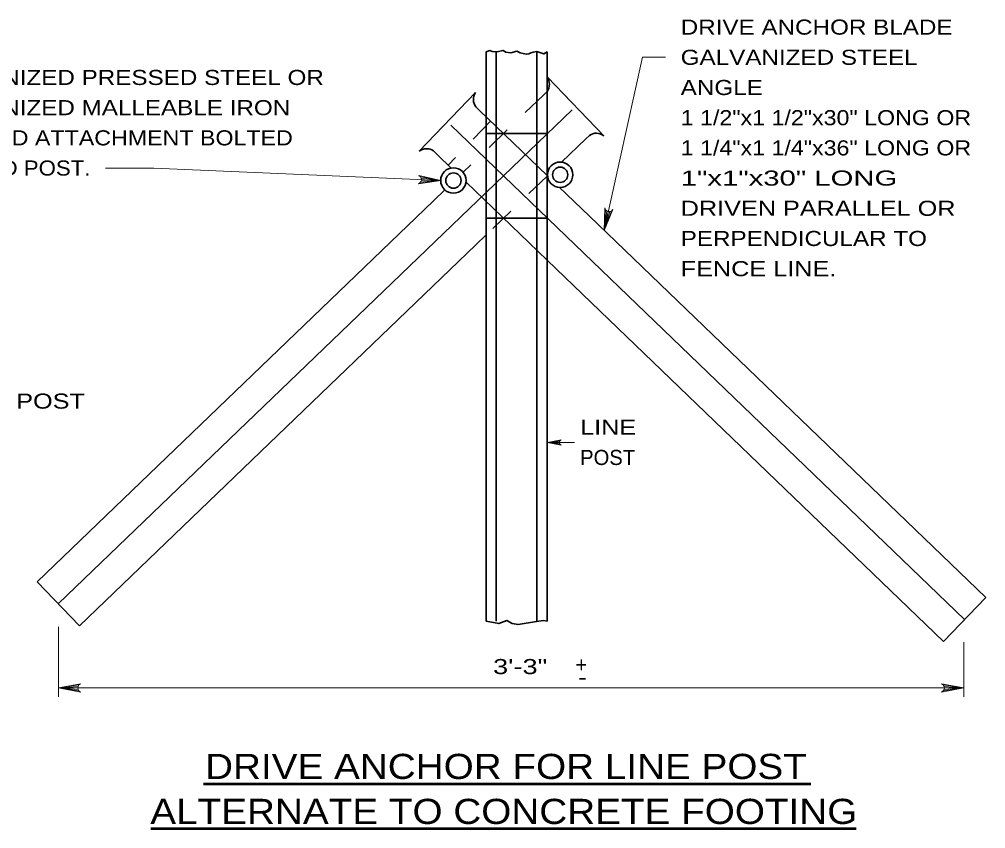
# Model space of a CAD drawing. Extents: x -29.89 to -22.78, y 99.65 to 109.34.
# Drawn here: x -26.626 to -22.784, y 106.12 to 109.336 of the extents above; entities that cross this region are included whole.
import ezdxf
from ezdxf.enums import TextEntityAlignment as Align

# ---------------------------------------------------------------- set-up
doc = ezdxf.new("R2010")
doc.units = 0
doc.header["$LTSCALE"] = 0.024
doc.linetypes.add('SHORT_DASHED', pattern=[2.7, 1.5, -1.2])
for name, color, linetype, lineweight in [('1', 7, 'Continuous', 35), ('10', 7, 'Continuous', 13), ('12', 7, 'Continuous', 53)]:
    doc.layers.add(name, color=color, linetype=linetype, lineweight=lineweight)

msp = doc.modelspace()

# ---------------------------------------------------------------- linework, layer by layer
at = {"layer": '1'}
for p, q in [((-24.7701, 106.94477), (-24.7701, 109.2074)), ((-24.72971, 106.94477), (-24.72971, 109.2074)), ((-24.56808, 106.94477), (-24.56808, 109.2074)), ((-24.52769, 106.94477), (-24.52769, 109.2074)), ((-24.52656, 109.1066), (-24.30254, 108.87362)), ((-24.81221, 109.04504), (-25.03625, 108.81206)), ((-26.47085, 107.0129), (-24.4284, 108.97679)), ((-24.79654, 108.97392), (-24.8111, 108.98792)), ((-24.52769, 108.71542), (-24.79654, 108.97392)), ((-22.86792, 106.95133), (-24.91037, 108.91523)), ((-24.7701, 108.88246), (-24.52769, 108.88246)), ((-24.7701, 106.94477), (-24.7701, 108.86681)), ((-24.72971, 106.94477), (-24.72971, 108.86681)), ((-24.56808, 106.94477), (-24.56808, 108.86681)), ((-24.52769, 106.94477), (-24.52769, 108.86681)), ((-24.46981, 108.76883), (-24.37423, 108.86073)), ((-24.37423, 108.86073), (-24.35967, 108.87473)), ((-24.96456, 108.79917), (-24.97912, 108.81317)), ((-24.90865, 108.7454), (-24.96456, 108.79917)), ((-24.97912, 108.61542), (-24.93429, 108.65852)), ((-24.52769, 108.3791), (-24.84996, 108.68898)), ((-24.35967, 108.55385), (-24.4799, 108.66946)), ((-26.55487, 107.10027), (-24.97912, 108.61542)), ((-24.7701, 108.54615), (-24.52769, 108.54615)), ((-22.78392, 107.03871), (-24.35967, 108.55385)), ((-24.8111, 108.44067), (-24.7701, 108.48008)), ((-26.38685, 106.92552), (-24.8111, 108.44067)), ((-22.95194, 106.86396), (-24.52769, 108.3791)), ((-26.55487, 107.10027), (-26.38685, 106.92552)), ((-22.78392, 107.03871), (-22.95194, 106.86396))]:
    msp.add_line(p, q, dxfattribs=at)
at = {"layer": '1', "linetype": 'SHORT_DASHED'}
for p, q in [((-24.54225, 109.03548), (-24.8616, 108.72842)), ((-24.54225, 109.03548), (-24.52769, 109.04948)), ((-24.75285, 108.93192), (-24.92087, 108.75717)), ((-24.52769, 108.71317), (-24.7701, 108.48008))]:
    msp.add_line(p, q, dxfattribs=at)
at = {"layer": '1'}
for centre, radius in [((-24.47554, 108.71865), 0.05051), ((-24.90003, 108.69564), 0.05051), ((-24.47554, 108.71865), 0.0303), ((-24.47554, 108.71865), 0.0303), ((-24.90003, 108.69564), 0.0303)]:
    msp.add_circle(centre, radius, dxfattribs=at)
for centre, radius, start, end in [((-24.57001, 109.07889), 0.05153, 325.20718, 32.54408), ((-24.76877, 109.01733), 0.05153, 147.45592, 214.79282), ((-24.33185, 108.83591), 0.04776, 52.13425, 125.61711), ((-25.00693, 108.77435), 0.04776, 54.38289, 127.86575)]:
    msp.add_arc(centre, radius, start, end, dxfattribs=at)
at = {"layer": '10'}
for p, q in [((-24.41896, 107.65429), (-24.52769, 107.65429)), ((-26.4705, 106.64312), (-26.4705, 106.92198)), ((-22.87112, 106.64312), (-22.87112, 106.86042)), ((-26.4705, 106.67948), (-22.87112, 106.67948))]:
    msp.add_line(p, q, dxfattribs=at)
at = {"layer": '10', "lineweight": 35}
for points in [[(-24.7701, 109.2074), (-24.75556, 109.21231), (-24.7454, 109.20796), (-24.72794, 109.2065), (-24.70248, 109.21304), (-24.69231, 109.20577), (-24.67194, 109.20358), (-24.64796, 109.21012), (-24.63413, 109.20358), (-24.6225, 109.20067), (-24.61013, 109.19777), (-24.60069, 109.19923), (-24.59196, 109.20285), (-24.58323, 109.20577), (-24.56796, 109.20796), (-24.54106, 109.1985), (-24.52769, 109.2074)], [(-24.7701, 106.94477), (-24.71956, 106.93492), (-24.68725, 106.94704), (-24.66704, 106.93492), (-24.64281, 106.93088), (-24.5701, 106.943), (-24.54183, 106.94704), (-24.52769, 106.94477)]]:
    msp.add_lwpolyline(points, dxfattribs=at)
at = {"layer": '10'}
for points in [[(-24.05702, 109.18537), (-24.14865, 109.18537), (-24.30092, 108.49735)], [(-26.28363, 108.74531), (-26.09121, 108.74531), (-24.95052, 108.69565)], [(-24.95052, 108.69565), (-25.03944, 108.68294), (-25.03244, 108.68735), (-25.02867, 108.69312), (-25.0274, 108.69898), (-25.02815, 108.70494), (-25.0314, 108.711), (-25.038, 108.71602), (-24.95052, 108.69565), (-25.0314, 108.711), (-25.02815, 108.70494), (-24.95052, 108.69565), (-25.0274, 108.69898), (-25.02867, 108.69312), (-24.95052, 108.69565), (-25.03244, 108.68735)], [(-24.30092, 108.49735), (-24.298, 108.5871), (-24.29487, 108.57946), (-24.28985, 108.57475), (-24.28429, 108.57248), (-24.27829, 108.57219), (-24.27175, 108.57433), (-24.26569, 108.57996), (-24.30092, 108.49735), (-24.27175, 108.57433), (-24.27829, 108.57219), (-24.30092, 108.49735), (-24.28429, 108.57248), (-24.28985, 108.57475), (-24.30092, 108.49735), (-24.29487, 108.57946)], [(-24.52769, 107.65429), (-24.47121, 107.6649), (-24.47556, 107.66187), (-24.47779, 107.65808), (-24.47844, 107.65429), (-24.47779, 107.65052), (-24.47556, 107.64673), (-24.47121, 107.64371), (-24.52769, 107.65429), (-24.47556, 107.64673), (-24.47779, 107.65052), (-24.52769, 107.65429), (-24.47844, 107.65429), (-24.47779, 107.65808), (-24.52769, 107.65429), (-24.47556, 107.66187)], [(-26.4705, 106.67948), (-26.38223, 106.69602), (-26.38904, 106.69131), (-26.39254, 106.6854), (-26.39356, 106.67948), (-26.39254, 106.67356), (-26.38904, 106.66765), (-26.38223, 106.66294), (-26.4705, 106.67948), (-26.38904, 106.66765), (-26.39254, 106.67356), (-26.4705, 106.67948), (-26.39356, 106.67948), (-26.39254, 106.6854), (-26.4705, 106.67948), (-26.38904, 106.69131)], [(-22.87112, 106.67948), (-22.9594, 106.66294), (-22.95258, 106.66765), (-22.94908, 106.67356), (-22.94806, 106.67948), (-22.94908, 106.6854), (-22.95258, 106.69131), (-22.9594, 106.69602), (-22.87112, 106.67948), (-22.95258, 106.69131), (-22.94908, 106.6854), (-22.87112, 106.67948), (-22.94806, 106.67948), (-22.94908, 106.67356), (-22.87112, 106.67948), (-22.95258, 106.66765)]]:
    msp.add_lwpolyline(points, dxfattribs=at)
at = {"layer": '12'}
for p, q in [((-25.89415, 106.29865), (-23.47846, 106.29865)), ((-26.10365, 106.11985), (-23.29933, 106.11985))]:
    msp.add_line(p, q, dxfattribs=at)

# ---------------------------------------------------------------- texts
for s, width, p in [('DRIVE ANCHOR BLADE', 1.2, (-23.99641, 109.27537)), ('GALVANIZED STEEL', 1.2, (-23.99641, 109.15537)), ('GALVANIZED PRESSED STEEL OR', 1.2, (-27.01495, 109.0753)), ('ANGLE ', 1.2, (-23.99641, 109.03538)), ('GALVANIZED MALLEABLE IRON', 1.2, (-27.01495, 108.9553)), ('1 1/2"x1 1/2"x30" LONG OR', 1.15, (-23.99641, 108.91537)), ('SLOTTED ATTACHMENT BOLTED', 1.15, (-27.01495, 108.8353)), ('1 1/4"x1 1/4"x36" LONG OR', 1.15, (-23.99641, 108.79537)), ('AROUND POST.', 1.1, (-27.01495, 108.7153)), ('1"x1"x30" LONG ', 1.45, (-23.99641, 108.67538)), ('DRIVEN PARALLEL OR ', 1.25, (-23.99641, 108.55537)), ('PERPENDICULAR TO ', 1.2, (-23.99641, 108.43537)), ('FENCE LINE.', 1.25, (-23.99641, 108.31538)), ('LINE POST', 1.25, (-26.88914, 107.78907)), ('LINE', 1.25, (-24.39623, 107.68512))]:
    msp.add_text(s, height=0.06, dxfattribs=dict(at, width=width)).set_placement(p)
msp.add_text('POST', height=0.06, dxfattribs=at).set_placement((-24.39623, 107.56512))
for s, height, width, p in [('3\'-3"', 0.06, 1.35, (-24.63464, 106.73403)), ('-', 0.06061, 1.3, (-24.3872, 106.6915)), ('DRIVE ANCHOR FOR LINE POST', 0.1, 1.15, (-24.69111, 106.31724)), ('ALTERNATE TO CONCRETE FOOTING', 0.1, 1.15, (-24.69969, 106.13846))]:
    msp.add_text(s, height=height, dxfattribs=dict(at, width=width)).set_placement(p, align=Align.CENTER)
msp.add_text('+', height=0.06, dxfattribs=at).set_placement((-24.39182, 106.7419), align=Align.CENTER)

doc.saveas('drawing.dxf')
